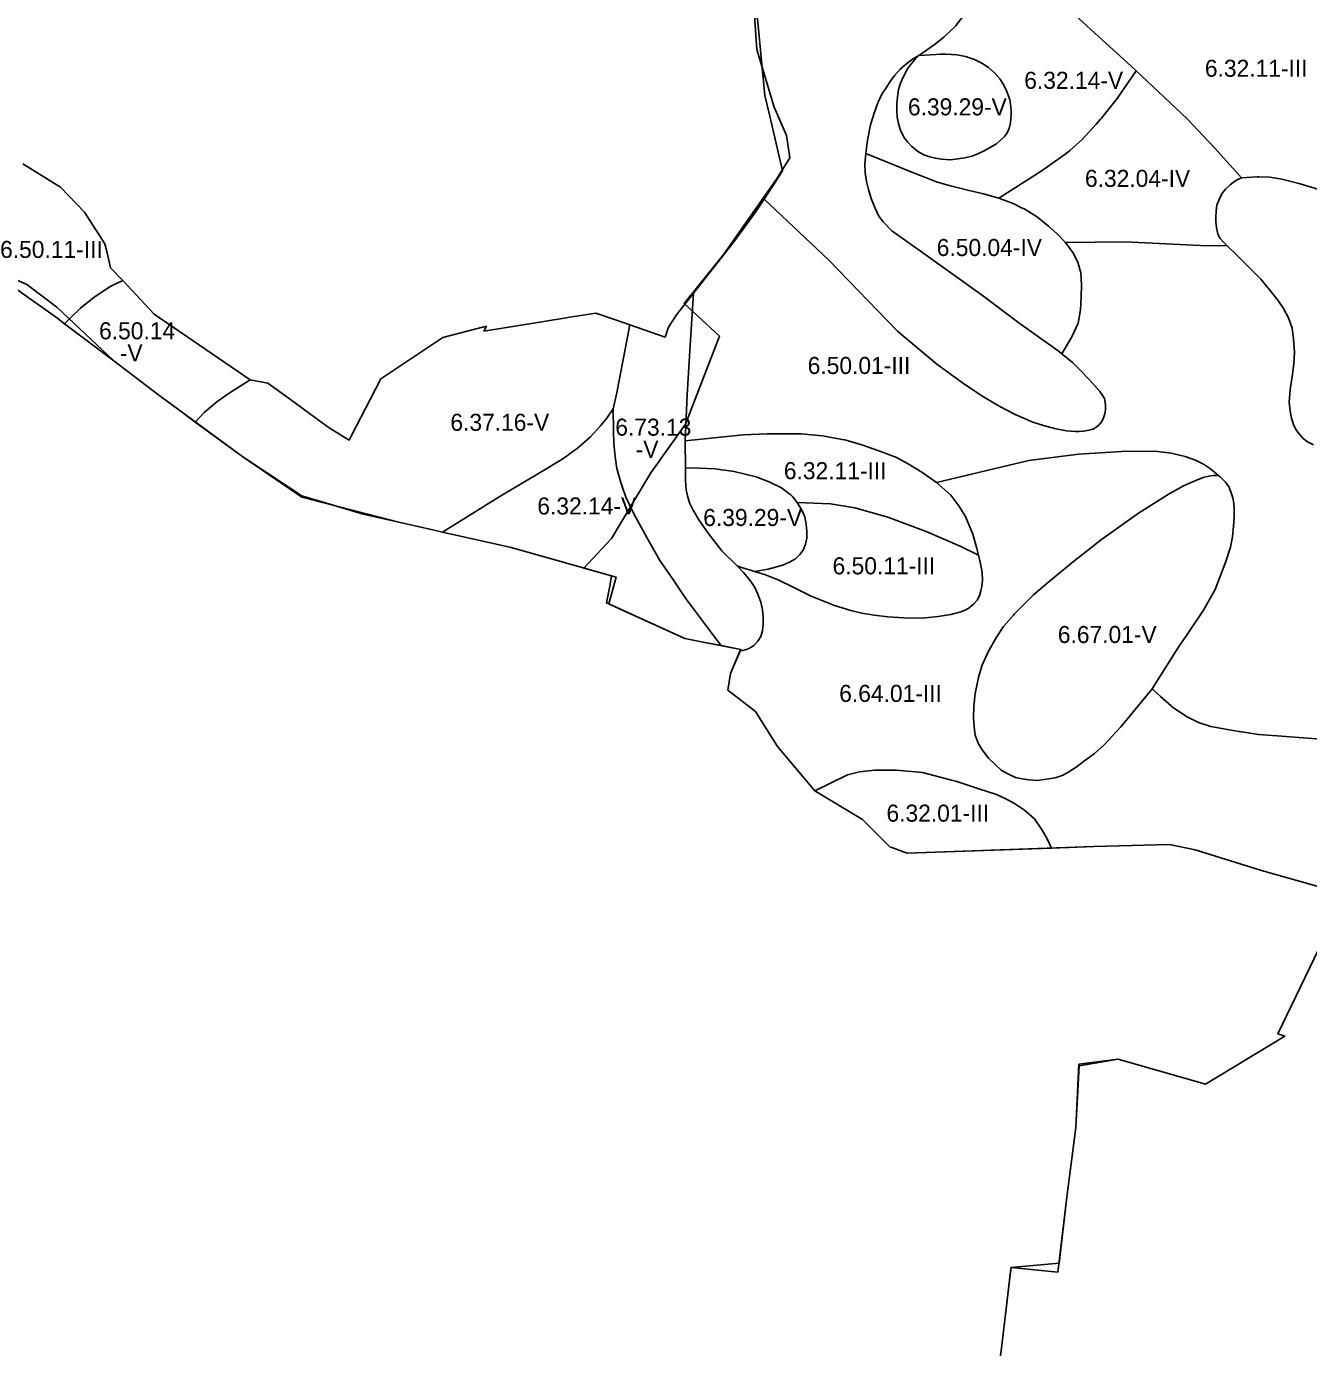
# Model space of a CAD drawing. Extents: x -555156 to -540209, y -1046851 to -1035695.
# Drawn here: x -544725 to -543973, y -1040556 to -1039781 of the extents above; entities that cross this region are included whole.
import ezdxf

# ---------------------------------------------------------------- set-up
doc = ezdxf.new("R2010")
doc.units = 0
for name, color, linetype in [('Vrstva 27', 7, 'Continuous'), ('Vrstva 28', 7, 'Continuous'), ('Vrstva 29', 7, 'Continuous')]:
    doc.layers.add(name, color=color, linetype=linetype)

msp = doc.modelspace()

# ---------------------------------------------------------------- linework, layer by layer
at = {"layer": 'Vrstva 28'}
for points in [[(-544286.59, -1039694.27), (-544280.35, -1039698.73), (-544269.21, -1039706.69), (-544264.36, -1039710.16), (-544265.92, -1039711.95), (-544276.58, -1039723.86), (-544279.1, -1039726.68), (-544302, -1039751.89), (-544311.24, -1039762.06), (-544304.47, -1039768.49), (-544295.86, -1039776.66), (-544291.48, -1039821.68), (-544288.66, -1039833.78), (-544281.17, -1039865.86), (-544284.72, -1039871.32), (-544291.97, -1039882.48)], [(-544201.25, -1039798.25), (-544194.18, -1039793.24), (-544192.31, -1039791.91), (-544186.48, -1039787.42), (-544179.61, -1039780.7), (-544178.71, -1039779.6), (-544176.7, -1039777.14), (-544172.29, -1039771.73), (-544166.02, -1039762.76), (-544160.19, -1039753.5), (-544155.72, -1039746.92), (-544154.02, -1039744.41), (-544152.79, -1039742.56), (-544151.53, -1039740.66)], [(-544073.71, -1039807.24), (-544076.78, -1039804.44), (-544093.62, -1039789.07), (-544109.46, -1039774.6), (-544113.22, -1039771.17), (-544128.27, -1039759.4), (-544139.32, -1039751.03), (-544151.53, -1039740.66)], [(-544178.38, -1039858.73), (-544174.2, -1039858.22), (-544170.19, -1039857.28), (-544166.61, -1039855.91), (-544162.59, -1039853.95), (-544158.84, -1039851.81), (-544155.77, -1039849.93), (-544153.46, -1039847.97), (-544151.16, -1039845.92), (-544149.45, -1039843.53), (-544148.34, -1039841.05), (-544147.41, -1039837.74), (-544146.98, -1039832.87), (-544147.09, -1039830.97), (-544147.24, -1039828.26), (-544147.83, -1039824.16), (-544149.54, -1039819.29), (-544151.5, -1039815.28), (-544153.72, -1039811.86), (-544156.71, -1039808.62), (-544160.38, -1039805.2), (-544164.31, -1039802.64), (-544168.49, -1039800.5), (-544173.87, -1039798.79), (-544178.82, -1039797.86), (-544185.39, -1039797.34), (-544188.63, -1039797.43), (-544191.28, -1039797.51), (-544201.25, -1039798.25)], [(-544232.39, -1039855.67), (-544231.38, -1039847.89), (-544231.37, -1039847.81), (-544229.57, -1039838.85), (-544227.27, -1039831.42), (-544225.32, -1039826), (-544222.84, -1039820.88), (-544220.37, -1039817.12), (-544218.06, -1039813.53), (-544215.24, -1039809.78), (-544212.17, -1039806.28), (-544208.33, -1039802.86), (-544205, -1039800.38), (-544201.25, -1039798.25)], [(-544201.25, -1039798.25), (-544203.37, -1039800.38), (-544205.59, -1039802.86), (-544207.9, -1039805.93), (-544210.2, -1039810.46), (-544211.99, -1039814.39), (-544213.1, -1039818.06), (-544213.7, -1039822.5), (-544214.13, -1039826.43), (-544214.13, -1039830.53), (-544213.87, -1039834.45), (-544213.12, -1039838.15), (-544211.93, -1039842.25), (-544209.54, -1039846.69), (-544207.83, -1039848.91), (-544205.36, -1039851.64), (-544201.86, -1039854.54), (-544198.27, -1039856.42), (-544194.77, -1039857.7), (-544191.53, -1039858.47), (-544187.86, -1039858.9), (-544182.74, -1039859.33), (-544178.38, -1039858.73)], [(-544154.39, -1039881.94), (-544128.87, -1039865.57), (-544114.75, -1039855.63), (-544112.66, -1039853.83), (-544105.34, -1039847.52), (-544097.16, -1039838.38), (-544094.82, -1039835.77), (-544094.1, -1039834.97), (-544084.95, -1039823.46), (-544073.71, -1039807.24)], [(-544073.71, -1039807.24), (-544044.08, -1039835.14), (-544027.61, -1039852.53), (-544012.06, -1039869.93)], [(-544117.37, -1039973.16), (-544119.5, -1039971.42), (-544142.51, -1039954.94), (-544163.94, -1039938.99), (-544199.75, -1039913.43), (-544217.02, -1039901.11), (-544222.22, -1039895.81), (-544224.62, -1039892.48), (-544227.01, -1039887.44), (-544229.23, -1039882.14), (-544230.77, -1039876.85), (-544231.88, -1039872.15), (-544232.65, -1039866.86), (-544232.9, -1039861.65), (-544232.39, -1039855.67)], [(-544154.39, -1039881.94), (-544163.35, -1039879.25), (-544171.72, -1039877.46), (-544181.87, -1039874.92), (-544185.49, -1039873.84), (-544190.84, -1039872.23), (-544197.41, -1039869.84), (-544204.43, -1039867), (-544232.39, -1039855.67)], [(-544668.11, -1039930.23), (-544675.23, -1039922.65), (-544677.32, -1039913.95), (-544678.59, -1039908.69), (-544690.61, -1039890.18), (-544704.7, -1039875.43), (-544726.8, -1039861.64)], [(-544012.06, -1039869.93), (-544013.73, -1039870.7), (-544015.95, -1039871.89), (-544018.6, -1039874.03), (-544019.23, -1039874.6), (-544021.33, -1039876.5), (-544022.34, -1039877.8), (-544023.46, -1039879.24), (-544025.17, -1039882.57), (-544026.37, -1039886.07), (-544026.88, -1039889.48), (-544026.96, -1039892.99), (-544027.05, -1039896.06), (-544026.93, -1039897.2), (-544026.71, -1039899.31), (-544025.85, -1039902.98), (-544024.4, -1039905.54)], [(-543928.99, -1039889.64), (-543937.72, -1039887.13), (-543949.97, -1039883.1), (-543964.16, -1039877.57), (-543971.18, -1039875.46), (-543977.6, -1039873.53), (-543983.71, -1039871.92), (-543988.36, -1039870.69), (-543995.38, -1039869.64), (-544001.77, -1039869.39), (-544002.85, -1039869.35), (-544012.06, -1039869.93)], [(-544291.97, -1039882.48), (-544296.95, -1039890.14), (-544310.31, -1039908.33), (-544333.47, -1039937.65)], [(-544291.97, -1039882.48), (-544254.25, -1039918.09), (-544213.74, -1039959.94), (-544190.73, -1039979.29), (-544175.62, -1039990.26), (-544164.18, -1039997.78), (-544154.2, -1040003.84), (-544144.81, -1040008.79), (-544134.31, -1040013.23), (-544128.08, -1040015.28), (-544121.59, -1040016.99), (-544114.68, -1040018.27)], [(-544115.26, -1039907.8), (-544120.04, -1039902.72), (-544125.11, -1039898.23), (-544131.69, -1039893), (-544139.15, -1039888.37), (-544141.37, -1039887.28), (-544145.15, -1039885.43), (-544145.88, -1039885.08), (-544154.39, -1039881.94)], [(-544024.4, -1039905.54), (-544022.61, -1039907.67), (-544020.31, -1039909.87)], [(-544020.31, -1039909.87), (-544035.94, -1039909.57), (-544080.38, -1039907.47), (-544115.26, -1039907.8)], [(-544111.46, -1039963.12), (-544107.87, -1039955.2), (-544106.38, -1039947.28), (-544105.93, -1039939.66), (-544105.78, -1039932.94), (-544106.23, -1039925.46), (-544106.72, -1039923.75), (-544107.94, -1039919.46), (-544110.92, -1039913.78), (-544115.26, -1039907.8)], [(-543969.77, -1040026.63), (-543973.18, -1040024.84), (-543975.83, -1040022.79), (-543978.22, -1040020.14), (-543980.1, -1040017.58), (-543981.55, -1040014.59), (-543982.66, -1040010.83), (-543983.34, -1040006.9), (-543983.94, -1040001.52), (-543983.51, -1039994.09), (-543982.33, -1039986.62), (-543981.28, -1039979.14), (-543980.99, -1039972.42), (-543980.98, -1039972.27), (-543981.43, -1039964.65), (-543982.33, -1039958.07), (-543984.42, -1039952.09), (-543987.41, -1039946.56), (-543990.69, -1039941.78), (-543995.32, -1039935.8), (-544000.7, -1039929.38), (-544004.32, -1039925.72), (-544008.8, -1039921.08), (-544014.78, -1039915.25), (-544020.31, -1039909.87)], [(-544702.25, -1039955.56), (-544707.07, -1039951.92), (-544727.65, -1039937.22), (-544737.18, -1039930.43), (-544750.69, -1039920.8), (-544762.14, -1039914.03)], [(-544750.69, -1039920.8), (-544724.3, -1039932.54), (-544706.73, -1039945.83), (-544673.44, -1039977.32), (-544647.06, -1039997.5), (-544633.96, -1040007.08), (-544597.74, -1040033.56), (-544563.16, -1040057.26), (-544506.22, -1040071.95), (-544485.44, -1040076.63), (-544480.66, -1040077.71), (-544440.31, -1040086.8), (-544378.8, -1040104.1), (-544379.8, -1040107.78), (-544383.09, -1040119.9), (-544338.48, -1040140.15), (-544327.72, -1040142.26), (-544305.7, -1040146.57), (-544311.69, -1040160.78), (-544313.15, -1040170.43), (-544296.97, -1040183.01), (-544284.05, -1040203.44), (-544262.29, -1040229.56), (-544234.34, -1040246.33), (-544218.11, -1040262.48), (-544217.12, -1040262.83), (-544208.12, -1040266.06), (-544098.65, -1040262.2), (-544054.28, -1040260.95), (-544039.21, -1040264.11), (-544000.24, -1040276.27), (-543946.79, -1040291.41)], [(-544668.11, -1039930.23), (-544675.08, -1039933.54), (-544684.9, -1039939.86), (-544692.92, -1039946.35), (-544698.64, -1039951.82)], [(-544593.31, -1039988.42), (-544649.68, -1039949.84), (-544668.11, -1039930.23)], [(-544333.47, -1039937.65), (-544343.41, -1039950.23), (-544348.11, -1039957.62), (-544350.01, -1039963.32), (-544370.73, -1039956.19)], [(-544338.34, -1040024.28), (-544337.19, -1039997.28), (-544335.37, -1039968.14), (-544333.47, -1039937.65)], [(-544698.64, -1039951.82), (-544702.25, -1039955.56)], [(-544370.73, -1039956.19), (-544379.76, -1039953.08), (-544390.62, -1039949.31), (-544405.89, -1039951.76), (-544407.97, -1039952.09), (-544421.15, -1039954.21), (-544450.37, -1039958.91), (-544456.29, -1039959.86), (-544454.8, -1039957.02), (-544456.33, -1039957.42), (-544480.43, -1039963.7), (-544512.68, -1039985.1), (-544516.71, -1039987.78), (-544523.06, -1040000), (-544533.79, -1040020.63), (-544535.41, -1040023.75), (-544547.07, -1040016.65), (-544555.58, -1040010.42), (-544569.82, -1040000), (-544582.97, -1039990.37), (-544593.31, -1039988.42)], [(-544625.59, -1040013.2), (-544633.96, -1040007.08), (-544647.06, -1039997.5), (-544673.44, -1039977.32), (-544702.25, -1039955.56)], [(-544370.73, -1039956.19), (-544377.88, -1039993.85), (-544378.29, -1039996.01), (-544380.53, -1040005.42)], [(-544117.37, -1039973.16), (-544111.46, -1039963.12)], [(-544114.68, -1040018.27), (-544109.56, -1040018.76), (-544107.17, -1040018.71), (-544104.59, -1040018.52), (-544101.47, -1040017.98), (-544099.27, -1040017.3), (-544097.32, -1040016.42), (-544095.61, -1040015.01), (-544094.05, -1040013), (-544093.12, -1040011.35), (-544092.15, -1040008.32), (-544091.71, -1040005.83), (-544091.71, -1040003.68), (-544091.86, -1040001.59), (-544092.39, -1039999.44), (-544093.61, -1039997.14), (-544095.12, -1039995.19), (-544097.99, -1039992.01), (-544101.49, -1039987.99), (-544106.35, -1039982.96), (-544111.13, -1039978.26), (-544117.37, -1039973.16)], [(-544620.28, -1040007.66), (-544612.94, -1040001.43), (-544605.08, -1039995.79), (-544593.31, -1039988.42)], [(-544480.66, -1040077.71), (-544446.4, -1040056.53), (-544425.34, -1040043.98), (-544410.1, -1040034.71), (-544401.44, -1040028.59), (-544393.97, -1040022.01), (-544388.15, -1040015.58), (-544384.26, -1040010.95), (-544380.53, -1040005.42)], [(-544380.53, -1040005.42), (-544380.4, -1040018.4), (-544380.1, -1040025.72), (-544379.35, -1040033.34), (-544378.31, -1040040.36), (-544376.07, -1040048.73), (-544375.24, -1040051.09), (-544373.08, -1040057.25), (-544368.3, -1040067.12), (-544360.83, -1040081.02), (-544353.21, -1040094.32), (-544345.21, -1040105.98), (-544341.17, -1040111.86), (-544337.46, -1040117.26), (-544319.23, -1040141.63)], [(-544625.59, -1040013.2), (-544620.28, -1040007.66)], [(-544480.66, -1040077.71), (-544485.44, -1040076.63), (-544506.22, -1040071.95), (-544527.11, -1040067.24), (-544550.62, -1040060.21), (-544562.52, -1040056.65), (-544563, -1040056.5), (-544597.74, -1040033.56), (-544625.59, -1040013.2)], [(-544338.34, -1040024.28), (-544304.23, -1040020.64), (-544290.19, -1040020.19), (-544270.17, -1040020.19), (-544257.78, -1040021.23), (-544246.1, -1040023.35), (-544244.63, -1040023.62), (-544242.71, -1040024.19), (-544234.03, -1040026.76), (-544222.53, -1040030.8), (-544214.31, -1040034.09), (-544207.44, -1040037.67), (-544199.52, -1040042.6), (-544190.86, -1040048.58)], [(-544338.04, -1040039.97), (-544338.34, -1040024.28)], [(-544025.23, -1040044.72), (-544030.25, -1040040.58), (-544034.29, -1040037.89), (-544038.92, -1040035.49), (-544045.04, -1040033.4), (-544053.25, -1040031.46), (-544061.32, -1040030.41), (-544079.24, -1040030.3), (-544107.48, -1040032.13), (-544113.67, -1040032.9), (-544136.75, -1040035.79), (-544190.86, -1040048.58)], [(-544307.86, -1040097.56), (-544316.86, -1040088.66), (-544324.86, -1040078.41), (-544329.9, -1040071.07), (-544333.65, -1040064.92), (-544335.79, -1040060.65), (-544336.98, -1040056.55), (-544337.67, -1040052.96), (-544338.01, -1040047.58), (-544338.04, -1040039.97)], [(-544272.53, -1040060.36), (-544275.37, -1040056.95), (-544276.26, -1040055.88), (-544277.44, -1040055.02), (-544281.79, -1040051.84), (-544288.66, -1040048.41), (-544296.57, -1040045.42), (-544309.57, -1040042.28), (-544320.77, -1040040.63), (-544329.88, -1040040.19), (-544338.04, -1040039.97)], [(-544025.23, -1040044.72), (-544026.85, -1040044.47), (-544028.51, -1040044.52), (-544031.05, -1040044.88), (-544034.37, -1040045.82), (-544039.67, -1040047.87), (-544039.73, -1040047.9), (-544045.9, -1040050.61), (-544054.43, -1040055.22), (-544072.42, -1040066.62), (-544094.08, -1040082.01), (-544110.51, -1040095.01), (-544124.7, -1040106.82), (-544133.94, -1040114.65), (-544143.87, -1040124.58), (-544145.04, -1040125.76), (-544145.74, -1040126.46), (-544151.56, -1040133.19), (-544155.74, -1040139.31), (-544160.67, -1040148.43), (-544164.11, -1040155.75), (-544166.2, -1040162.93), (-544166.23, -1040163.08), (-544168.14, -1040172.34), (-544168.89, -1040180.11), (-544169.16, -1040186.91), (-544168.74, -1040192.04), (-544168.14, -1040196.82), (-544166.52, -1040201.6), (-544164.13, -1040205.53), (-544160.29, -1040210.31), (-544156.36, -1040214.16), (-544152.86, -1040217.32), (-544149.11, -1040219.62), (-544144.58, -1040221.67), (-544140.57, -1040222.53), (-544136.47, -1040223.12), (-544131.52, -1040223.38), (-544126.49, -1040222.78)], [(-544064.32, -1040169.77), (-544048.34, -1040144.37), (-544044.66, -1040138.93), (-544042.66, -1040135.97), (-544034.3, -1040123.59), (-544027.42, -1040111.34), (-544021.16, -1040094.95), (-544018.51, -1040086.5), (-544017.32, -1040080.44), (-544016.63, -1040074.2), (-544016.29, -1040069.08), (-544016.29, -1040064.3), (-544016.55, -1040061.05), (-544017.06, -1040057.72), (-544018, -1040054.73), (-544018.97, -1040052.27), (-544019.28, -1040051.49), (-544021.33, -1040048.41), (-544024.28, -1040045.51), (-544025.23, -1040044.72)], [(-544190.86, -1040048.58), (-544182.49, -1040056.06), (-544177.72, -1040062.33), (-544173.83, -1040068.61), (-544169.65, -1040078.92), (-544167.11, -1040087.44)], [(-544272.53, -1040060.36), (-544269.84, -1040064.84), (-544268.11, -1040068.84), (-544267.25, -1040073.19), (-544266.91, -1040077.21), (-544267, -1040081.31), (-544267.68, -1040084.81), (-544269.05, -1040088.39), (-544271.01, -1040090.96), (-544273.57, -1040093.35), (-544277.16, -1040095.4), (-544280.57, -1040096.93), (-544284.5, -1040098.21), (-544289.68, -1040099.45)], [(-544166.23, -1040091.33), (-544176.89, -1040085.99), (-544197.02, -1040077.36), (-544219.5, -1040068.99), (-544238.84, -1040063.5), (-544252.96, -1040061.15), (-544272.53, -1040060.36)], [(-544317.22, -1040144.31), (-544327.72, -1040142.26), (-544338.48, -1040140.15), (-544376.78, -1040122.76), (-544384.41, -1040119.3), (-544382.72, -1040110.4), (-544382.11, -1040107.17), (-544381.4, -1040103.45), (-544440.31, -1040086.8), (-544480.66, -1040077.71)], [(-544166.23, -1040091.33), (-544165.32, -1040095.36), (-544164.12, -1040101.19), (-544163.85, -1040106.14), (-544164.28, -1040109.47), (-544164.79, -1040112.28), (-544165.73, -1040115.1), (-544167.01, -1040117.66), (-544168.89, -1040119.8), (-544171.79, -1040122.11), (-544174.01, -1040123.56), (-544177.17, -1040124.75), (-544182.46, -1040126.03), (-544189.8, -1040127.31)], [(-544167.11, -1040087.44), (-544166.23, -1040091.33)], [(-544305.99, -1040147.26), (-544304.87, -1040147.2), (-544304.54, -1040147.12), (-544303.17, -1040146.79), (-544300.69, -1040145.94), (-544299.6, -1040145.24), (-544298.05, -1040144.23), (-544297.49, -1040143.65), (-544295.57, -1040141.67), (-544293.95, -1040138.93), (-544292.92, -1040135.6), (-544292.58, -1040131.51), (-544292.5, -1040127.49), (-544292.92, -1040123.31), (-544293.86, -1040118.78), (-544295.57, -1040114.08), (-544297.53, -1040109.9), (-544300.43, -1040105.89), (-544304.13, -1040101.38), (-544304.76, -1040100.62), (-544306.65, -1040098.75), (-544307.86, -1040097.56)], [(-544297.45, -1040100.94), (-544303.29, -1040099.04), (-544306.34, -1040098.05), (-544307.86, -1040097.56)], [(-544289.68, -1040099.45), (-544297.45, -1040100.94)], [(-544189.8, -1040127.31), (-544199.36, -1040128.17), (-544209.95, -1040128.08), (-544219.48, -1040127.39), (-544227.39, -1040126.5), (-544234.56, -1040125.3), (-544241.14, -1040123.81), (-544250.7, -1040120.82), (-544264.44, -1040115.29), (-544274.15, -1040110.36), (-544283.41, -1040105.87), (-544291.17, -1040102.89), (-544297.45, -1040100.94)], [(-544319.23, -1040141.63), (-544317.22, -1040144.31)], [(-544305.99, -1040147.26), (-544305.7, -1040146.57), (-544317.22, -1040144.31)], [(-544262.29, -1040229.56), (-544284.05, -1040203.44), (-544296.97, -1040183.01), (-544313.15, -1040170.43), (-544311.69, -1040160.78), (-544305.99, -1040147.26)], [(-544126.49, -1040222.78), (-544121.2, -1040221.93), (-544117.18, -1040220.56), (-544113.77, -1040218.77), (-544108.91, -1040215.69), (-544104.55, -1040212.36), (-544098.24, -1040207.58), (-544092.43, -1040202.46), (-544082.77, -1040191.93), (-544078.92, -1040187.31), (-544064.32, -1040169.77)], [(-543957.8, -1040199.74), (-543991.09, -1040197.27), (-543996.51, -1040196.87), (-544001.98, -1040196.46), (-544013, -1040194.74), (-544013.68, -1040194.63), (-544020.21, -1040193.62), (-544029.92, -1040191.83), (-544037.23, -1040189.44), (-544043.81, -1040186.15), (-544051.57, -1040181.07), (-544059.49, -1040174.19), (-544064.32, -1040169.77)], [(-544262.29, -1040229.56), (-544243.02, -1040220.24), (-544235.93, -1040218.36), (-544226.97, -1040217.42), (-544220.48, -1040217.42), (-544214.25, -1040217.42), (-544198.98, -1040218.79), (-544181.24, -1040223.38), (-544179.51, -1040223.83), (-544174.79, -1040225.4), (-544166.11, -1040228.27), (-544155.7, -1040231.77), (-544150.19, -1040234.16), (-544145.07, -1040236.97), (-544139.27, -1040240.9), (-544133.38, -1040246.03), (-544129.28, -1040251.92), (-544128.66, -1040252.98), (-544126.12, -1040257.3), (-544125.98, -1040257.6), (-544123.46, -1040263.07)], [(-544123.46, -1040263.07), (-544208.12, -1040266.06), (-544217.12, -1040262.83), (-544218.11, -1040262.48), (-544233.72, -1040246.94), (-544234.34, -1040246.33), (-544262.29, -1040229.56)], [(-543946.79, -1040291.41), (-544000.24, -1040276.27), (-544039.21, -1040264.11), (-544054.28, -1040260.95), (-544098.65, -1040262.2), (-544123.46, -1040263.07)], [(-544166.22, -1040637.59), (-544159.37, -1040602.39), (-544152.78, -1040556.39), (-544148.25, -1040518.25), (-544148.05, -1040516.52), (-544147.1, -1040509.05), (-544119.61, -1040511.85), (-544114.36, -1040467.79), (-544109.21, -1040427.07), (-544107.28, -1040390.92), (-544084.37, -1040386.84), (-544033.06, -1040401.65), (-543986.48, -1040373.41), (-543990.67, -1040372.14), (-543961.4, -1040311.25), (-543946.79, -1040291.41)], [(-543961.4, -1040311.25), (-543990.67, -1040372.14), (-543986.48, -1040373.41), (-544033.06, -1040401.65), (-544084.37, -1040386.84), (-544107.36, -1040389.92), (-544109.21, -1040427.07), (-544114.36, -1040467.79), (-544118.98, -1040506.54), (-544147.1, -1040509.05), (-544147.59, -1040512.94), (-544148.05, -1040516.52), (-544148.45, -1040519.91), (-544152.78, -1040556.39)]]:
    msp.add_lwpolyline(points, dxfattribs=at)
at = {"layer": 'Vrstva 29'}
for points in [[(-544299.3, -1039749.2), (-544296.18, -1039794.66), (-544286.12, -1039828.41), (-544278.93, -1039845.05), (-544276.83, -1039858.26), (-544284.79, -1039870.76), (-544315.63, -1039914.76), (-544338.794655, -1039943.733748), (-544318.206909, -1039962.789978), (-544337.992981, -1040014.414001), (-544358.377991, -1040043.036011), (-544381.507019, -1040081.591003), (-544397.662566, -1040098.853637), (-544381.4, -1040103.45), (-544382.11, -1040107.17), (-544382.72, -1040110.4), (-544384.41, -1040119.3), (-544383.09, -1040119.9), (-544376.781628, -1040122.763585), (-544338.48, -1040140.15), (-544327.72, -1040142.26), (-544317.220976, -1040144.314986), (-544305.7, -1040146.57), (-544305.990729, -1040147.259693), (-544311.69, -1040160.78), (-544313.15, -1040170.43), (-544296.97, -1040183.01), (-544284.05, -1040203.44), (-544262.29, -1040229.56), (-544234.34, -1040246.33), (-544233.723472, -1040246.943489), (-544218.11, -1040262.48), (-544217.12, -1040262.83), (-544208.12, -1040266.06), (-544123.45983, -1040263.074815), (-544098.65, -1040262.2), (-544054.28, -1040260.95), (-544039.21, -1040264.11), (-544000.24, -1040276.27), (-543948.969538, -1040290.792634)], [(-543961.4, -1040311.25), (-543990.67, -1040372.14), (-543986.48, -1040373.41), (-544033.06, -1040401.65), (-544084.37, -1040386.84), (-544107.36, -1040389.92), (-544109.21, -1040427.07), (-544114.36, -1040467.79), (-544118.98, -1040506.54), (-544147.1, -1040509.05), (-544147.594637, -1040512.93941), (-544148.05, -1040516.52), (-544148.254073, -1040518.249519), (-544148.45, -1040519.91), (-544152.78, -1040556.39)]]:
    msp.add_lwpolyline(points, dxfattribs=at)

# ---------------------------------------------------------------- texts
at = {"layer": 'Vrstva 27'}
for s, p in [('6.32.11-III', (-544033.446548, -1039810.67)), ('6.32.14-V', (-544139.410884, -1039817.74)), ('6.39.29-V', (-544207.620459, -1039833.32)), ('6.32.04-IV', (-544103.797119, -1039875.26)), ('6.50.04-IV', (-544190.717119, -1039915.81)), ('6.50.11-III', (-544740.076548, -1039916.93)), ('6.50.14', (-544682.023149, -1039964.67)), ('-V', (-544669.827104, -1039977.67)), ('6.50.01-III', (-544266.406548, -1039985.01)), ('6.37.16-V', (-544475.977974, -1040018.34)), ('6.73.13', (-544379.242427, -1040021.2)), ('-V', (-544367.291743, -1040034.2)), ('6.32.11-III', (-544280.376548, -1040046.74)), ('6.32.14-V', (-544424.970884, -1040067.43)), ('6.39.29-V', (-544327.670459, -1040074.18)), ('6.50.11-III', (-544251.816548, -1040102.54)), ('6.67.01-V', (-544119.701006, -1040142.82)), ('6.64.01-III', (-544247.916548, -1040177.38)), ('6.32.01-III', (-544220.216548, -1040247.62))]:
    msp.add_text(s, height=10, dxfattribs=at).set_placement(p)

doc.saveas('drawing.dxf')
